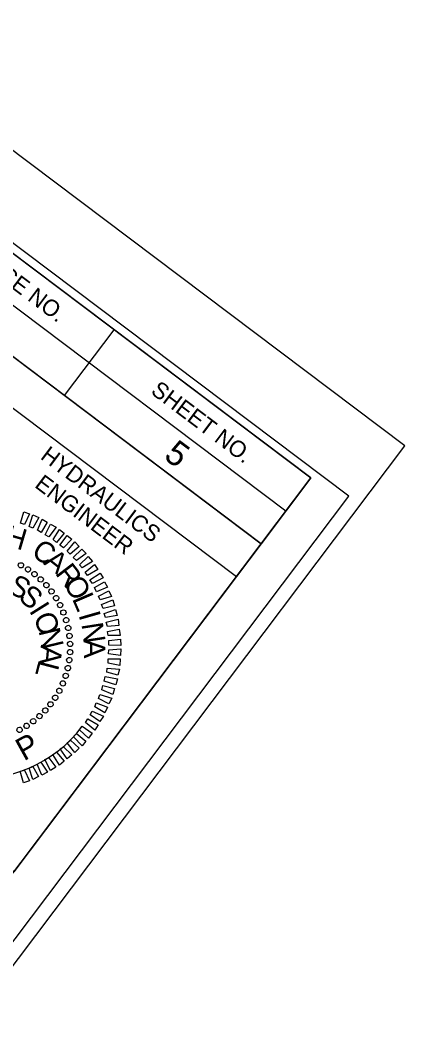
# Model space of a CAD drawing. Extents: x 2296955 to 2298159, y 600182 to 601317.
# Drawn here: x 2298088.7 to 2298159, y 600604.2 to 600787.1 of the extents above; entities that cross this region are included whole.
import ezdxf

# ---------------------------------------------------------------- set-up
doc = ezdxf.new("R2010")
doc.units = 0
for name, color, linetype in [('Exist DTM Drainline Cogo Comment', 7, 'Continuous'), ('Exist DTM Drainline Cogo Elevation', 7, 'Continuous'), ('Exist Roads Curbs Cogo Point CELL', 7, 'Continuous'), ('Exist Roads EOP Cogo Comment', 7, 'Continuous'), ('Exist Roads EOP Cogo Point CELL', 7, 'Continuous'), ('Exist Roads EOP Other Cogo Number', 7, 'Continuous')]:
    doc.layers.add(name, color=color, linetype=linetype)

msp = doc.modelspace()

# ---------------------------------------------------------------- linework, layer by layer
at = {"layer": 'Exist DTM Drainline Cogo Comment'}
msp.add_lwpolyline([(2298148.7, 600700.2), (2297350.15, 601301.97), (2296969.16, 600796.39), (2297767.7, 600194.63)], close=True, dxfattribs=at)
at = {"layer": 'Exist DTM Drainline Cogo Elevation'}
for p, q in [((2298041.39, 600769.72), (2298137.25, 600697.48)), ((2298036.88, 600763.73), (2298132.74, 600691.49)), ((2298036.88, 600763.73), (2298132.74, 600691.49)), ((2298105.83, 600730.55), (2298096.8, 600718.58)), ((2298132.74, 600691.49), (2298128.23, 600685.5))]:
    msp.add_line(p, q, dxfattribs=at)
for points in [[(2298141.78, 600703.5), (2297423.02, 601245.14), (2297043.87, 600742.01), (2297762.63, 600200.36)], [(2298045.93, 600775.73), (2298141.78, 600703.5), (2298132.74, 600691.49), (2298036.88, 600763.73)], [(2298080.31, 600721.61), (2298128.23, 600685.5), (2298087.6, 600631.6), (2298039.68, 600667.71)]]:
    msp.add_lwpolyline(points, close=True, dxfattribs=at)
at = {"layer": 'Exist Roads Curbs Cogo Point CELL'}
msp.add_lwpolyline([(2298158.96, 600709.34), (2297352.03, 601317.42), (2296954.82, 600790.33), (2297761.75, 600182.24)], close=True, dxfattribs=at)
at = {"layer": 'Exist Roads EOP Cogo Comment'}
msp.add_arc((2298080.95, 600672.61), 23.96, 142.9991, 322.9991, dxfattribs=at)
at = {"layer": 'Exist Roads EOP Other Cogo Number'}
for p, q in [((2298088.9, 600687.54), (2298088.9, 600687.54)), ((2298090.18, 600686.83), (2298090.18, 600686.83)), ((2298091.39, 600685.96), (2298091.39, 600685.96)), ((2298092.51, 600684.98), (2298092.51, 600684.98)), ((2298093.53, 600683.92), (2298093.53, 600683.92)), ((2298094.48, 600682.83), (2298094.48, 600682.83)), ((2298095.32, 600681.6), (2298095.32, 600681.6)), ((2298096.04, 600680.3), (2298096.04, 600680.3)), ((2298096.68, 600678.97), (2298096.68, 600678.97)), ((2298097.14, 600677.56), (2298097.14, 600677.56)), ((2298097.54, 600676.12), (2298097.54, 600676.12)), ((2298097.77, 600674.69), (2298097.77, 600674.69)), ((2298097.87, 600671.74), (2298097.87, 600671.74)), ((2298097.9, 600673.19), (2298097.9, 600673.19)), ((2298097.71, 600670.24), (2298097.71, 600670.24)), ((2298097.46, 600668.79), (2298097.46, 600668.79)), ((2298097.08, 600667.38), (2298097.08, 600667.38)), ((2298095.87, 600664.66), (2298095.87, 600664.66)), ((2298096.55, 600666.01), (2298096.55, 600666.01)), ((2298095.16, 600663.38), (2298095.16, 600663.38)), ((2298093.32, 600661.05), (2298093.32, 600661.05)), ((2298094.29, 600662.17), (2298094.29, 600662.17)), ((2298091.16, 600659.08), (2298091.16, 600659.08)), ((2298092.26, 600660.03), (2298092.26, 600660.03)), ((2298089.93, 600658.23), (2298089.93, 600658.23))]:
    msp.add_line(p, q, dxfattribs=at)
for points in [[(2298088.8, 600695.26), (2298089.4, 600697.34), (2298090.42, 600696.96), (2298089.51, 600695.02)], [(2298090.36, 600694.64), (2298091.07, 600696.76), (2298092.13, 600696.26), (2298091.03, 600694.34)], [(2298091.88, 600693.96), (2298092.74, 600696.01), (2298093.69, 600695.42), (2298092.58, 600693.55)], [(2298093.29, 600693.14), (2298094.29, 600695.09), (2298095.29, 600694.51), (2298094, 600692.74)], [(2298094.74, 600692.26), (2298095.93, 600694.12), (2298096.8, 600693.42), (2298095.37, 600691.75)], [(2298096.01, 600691.26), (2298097.33, 600693.01), (2298098.2, 600692.32), (2298096.64, 600690.75)], [(2298097.3, 600690.16), (2298098.73, 600691.84), (2298099.5, 600691), (2298097.87, 600689.57)], [(2298098.43, 600688.97), (2298099.97, 600690.52), (2298100.76, 600689.71), (2298099.02, 600688.41)], [(2298099.58, 600687.64), (2298101.17, 600689.19), (2298101.93, 600688.28), (2298100.05, 600687.08)], [(2298100.61, 600686.32), (2298102.28, 600687.68), (2298102.91, 600686.78), (2298101.04, 600685.7)], [(2298101.46, 600684.92), (2298103.36, 600686.15), (2298103.87, 600685.26), (2298101.94, 600684.26)], [(2298102.29, 600683.49), (2298104.16, 600684.57), (2298104.71, 600683.57), (2298102.66, 600682.75)], [(2298103.06, 600681.94), (2298104.95, 600682.92), (2298105.41, 600681.86), (2298103.33, 600681.23)], [(2298103.56, 600680.42), (2298105.68, 600681.27), (2298105.96, 600680.17), (2298103.91, 600679.65)], [(2298104.06, 600678.78), (2298106.17, 600679.51), (2298106.43, 600678.38), (2298104.29, 600678.01)], [(2298104.45, 600677.17), (2298106.61, 600677.74), (2298106.77, 600676.6), (2298104.66, 600676.38)], [(2298104.71, 600675.49), (2298106.83, 600675.89), (2298106.99, 600674.75), (2298104.79, 600674.76)], [(2298104.92, 600673.81), (2298107.08, 600674.09), (2298107.1, 600672.94), (2298104.9, 600672.99)], [(2298104.94, 600672.15), (2298107.12, 600672.29), (2298107.04, 600671.12), (2298104.88, 600671.4)], [(2298104.81, 600670.52), (2298107.01, 600670.47), (2298106.91, 600669.27), (2298104.78, 600669.69)], [(2298104.62, 600668.8), (2298106.84, 600668.61), (2298106.56, 600667.51), (2298104.55, 600668.05)], [(2298104.28, 600667.24), (2298106.48, 600666.85), (2298106.18, 600665.72), (2298104.1, 600666.44)], [(2298103.81, 600665.61), (2298105.98, 600665.07), (2298105.65, 600664.01), (2298103.66, 600664.84)], [(2298103.27, 600663.99), (2298105.46, 600663.31), (2298104.95, 600662.3), (2298103.03, 600663.28)], [(2298101.89, 600660.97), (2298103.92, 600660.03), (2298103.31, 600659.05), (2298101.51, 600660.25)], [(2298102.62, 600662.45), (2298104.7, 600661.68), (2298104.17, 600660.64), (2298102.35, 600661.76)], [(2298101.07, 600659.56), (2298102.99, 600658.45), (2298102.35, 600657.5), (2298100.64, 600658.87)], [(2298100.08, 600658.19), (2298101.9, 600656.95), (2298101.21, 600656.03), (2298099.6, 600657.54)], [(2298097.93, 600655.67), (2298099.53, 600654.21), (2298098.74, 600653.37), (2298097.31, 600655.13)], [(2298099.04, 600656.86), (2298100.75, 600655.49), (2298100.03, 600654.64), (2298098.5, 600656.26)], [(2298095.35, 600653.43), (2298096.76, 600651.82), (2298095.9, 600651.07), (2298094.71, 600653.02)], [(2298096.68, 600654.46), (2298098.19, 600652.98), (2298097.31, 600652.21), (2298096.04, 600654.05)], [(2298092.54, 600651.66), (2298093.75, 600649.78), (2298092.71, 600649.25), (2298091.83, 600651.27)], [(2298093.97, 600652.44), (2298095.28, 600650.69), (2298094.3, 600650.12), (2298093.25, 600652.1)], [(2298089.55, 600650.15), (2298090.45, 600648.21), (2298089.34, 600647.86), (2298088.75, 600649.99)], [(2298091.07, 600650.83), (2298092.1, 600648.99), (2298091.06, 600648.46), (2298090.36, 600650.56)]]:
    msp.add_lwpolyline(points, close=True, dxfattribs=at)
for centre, major_axis in [((2298088.89, 600687.56), (0.228, 0.429)), ((2298090.17, 600686.81), (0.265, 0.408)), ((2298091.37, 600685.95), (0.299, 0.383)), ((2298092.49, 600684.99), (0.331, 0.355)), ((2298093.53, 600683.94), (0.361, 0.325)), ((2298094.47, 600682.8), (0.388, 0.292)), ((2298095.3, 600681.58), (0.412, 0.258)), ((2298096.03, 600680.3), (0.433, 0.221)), ((2298096.64, 600678.95), (0.451, 0.182)), ((2298097.14, 600677.56), (0.465, 0.142)), ((2298097.51, 600676.13), (0.475, 0.101)), ((2298097.75, 600674.67), (0.482, 0.059)), ((2298097.86, 600673.2), (0.486, 0.017)), ((2298097.85, 600671.72), (0.485, -0.025)), ((2298097.71, 600670.25), (0.481, -0.068)), ((2298097.44, 600668.8), (0.474, -0.109)), ((2298096.53, 600666), (0.447, -0.19)), ((2298097.05, 600667.38), (0.462, -0.15)), ((2298095.89, 600664.66), (0.429, -0.228)), ((2298094.29, 600662.19), (0.383, -0.299)), ((2298095.14, 600663.39), (0.408, -0.265)), ((2298093.33, 600661.07), (0.355, -0.331)), ((2298091.13, 600659.09), (0.292, -0.388)), ((2298092.27, 600660.03), (0.325, -0.361)), ((2298088.63, 600657.53), (0.221, -0.433)), ((2298089.92, 600658.25), (0.258, -0.412))]:
    msp.add_ellipse(centre, major_axis=major_axis, ratio=0.999708, dxfattribs=at)

# ---------------------------------------------------------------- texts
at = {"layer": 'Exist DTM Drainline Cogo Elevation'}
for s, height, p in [('PROJECT REFERENCE NO.', 3.0001, (2298053.42, 600763.55)), ('SHEET NO.', 3, (2298112.4, 600719.03)), ('HYDRAULICS', 3, (2298092.26, 600707.12)), ('ENGINEER', 3, (2298091.21, 600701.94))]:
    msp.add_text(s, height=height, rotation=322.9991, dxfattribs=at).set_placement(p)
at = {"layer": 'Exist Roads EOP Cogo Point CELL'}
msp.add_text('5', height=4.5, rotation=322.9991, dxfattribs=at).set_placement((2298114.75, 600707.15))
at = {"layer": 'Exist Roads EOP Other Cogo Number'}
for s, height, rotation, p in [('H', 3.85, 343.6186, (2298085.69, 600691.3)), ('C', 3.81, 329.219, (2298090.6, 600689.3)), ('A', 3.81, 322.0195, (2298092.85, 600687.85)), ('R', 3.83, 307.6202, (2298095.04, 600686.04)), ('S', 3.81, 330.2547, (2298086.28, 600682.83)), ('O', 3.86, 300.4203, (2298096.54, 600684.27)), ('S', 3.81, 320.8995, (2298088.24, 600681.4)), ('I', 3.86, 302.1887, (2298090.28, 600679.27)), ('L', 3.89, 293.22, (2298098.16, 600681.49)), ('I', 3.92, 286.0193, (2298099.37, 600678.55)), ('O', 3.89, 292.8326, (2298091.07, 600678.08)), ('N', 3.92, 283.4758, (2298092.06, 600675.64)), ('N', 3.93, 278.818, (2298099.9, 600676.84)), ('A', 3.93, 271.6163, (2298100.29, 600674.05)), ('A', 3.92, 264.7594, (2298092.54, 600673.08)), ('L', 3.88, 255.4, (2298092.19, 600670.43)), ('P', 4.13, 28.9814, (2298089.42, 600651.76))]:
    msp.add_text(s, height=height, rotation=rotation, dxfattribs=at).set_placement(p)

doc.saveas('drawing.dxf')
